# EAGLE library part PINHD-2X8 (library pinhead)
PIN HEADER
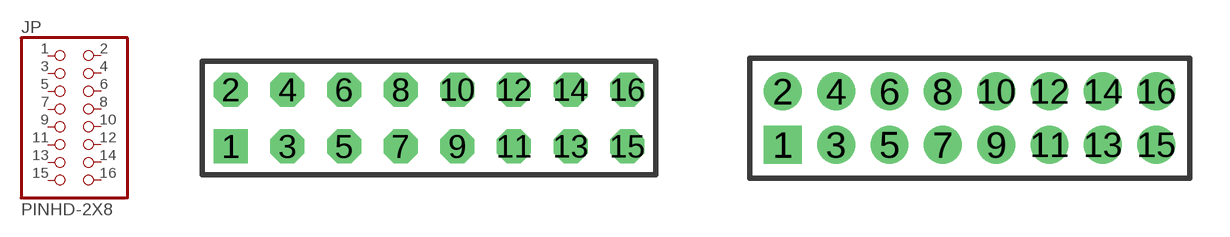
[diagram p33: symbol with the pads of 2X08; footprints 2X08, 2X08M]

Designator prefix JP

## PINHD-2X8  [2X08]
1  1  pas
2  2  pas
3  3  pas
4  4  pas
5  5  pas
6  6  pas
7  7  pas
8  8  pas
9  9  pas
10  10  pas
11  11  pas
12  12  pas
13  13  pas
14  14  pas
15  15  pas
16  16  pas

## PINHD-2X8M  [2X08M]
Pads as for 2X08

## Footprint 2X08 (pad centres in mm)
PIN HEADER - 0.1"
drill 1.016 square: 1 -8.89,-1.27
drill 1.016 octagon: 2 -8.89,1.27; 3 -6.35,-1.27; 4 -6.35,1.27; 5 -3.81,-1.27; 6 -3.81,1.27; 7 -1.27,-1.27; 8 -1.27,1.27; 9 1.27,-1.27; 10 1.27,1.27; 11 3.81,-1.27; 12 3.81,1.27; 13 6.35,-1.27; 14 6.35,1.27; 15 8.89,-1.27; 16 8.89,1.27

## Footprint 2X08M (pad centres in mm)
PIN HEADER - 2MM"
drill 0.914 square: 1 -7,-1
drill 0.914 round: 2 -7,1; 3 -5,-1; 4 -5,1; 5 -3,-1; 6 -3,1; 7 -1,-1; 8 -1,1; 9 1,-1; 10 1,1; 11 3,-1; 12 3,1; 13 5,-1; 14 5,1; 15 7,-1; 16 7,1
